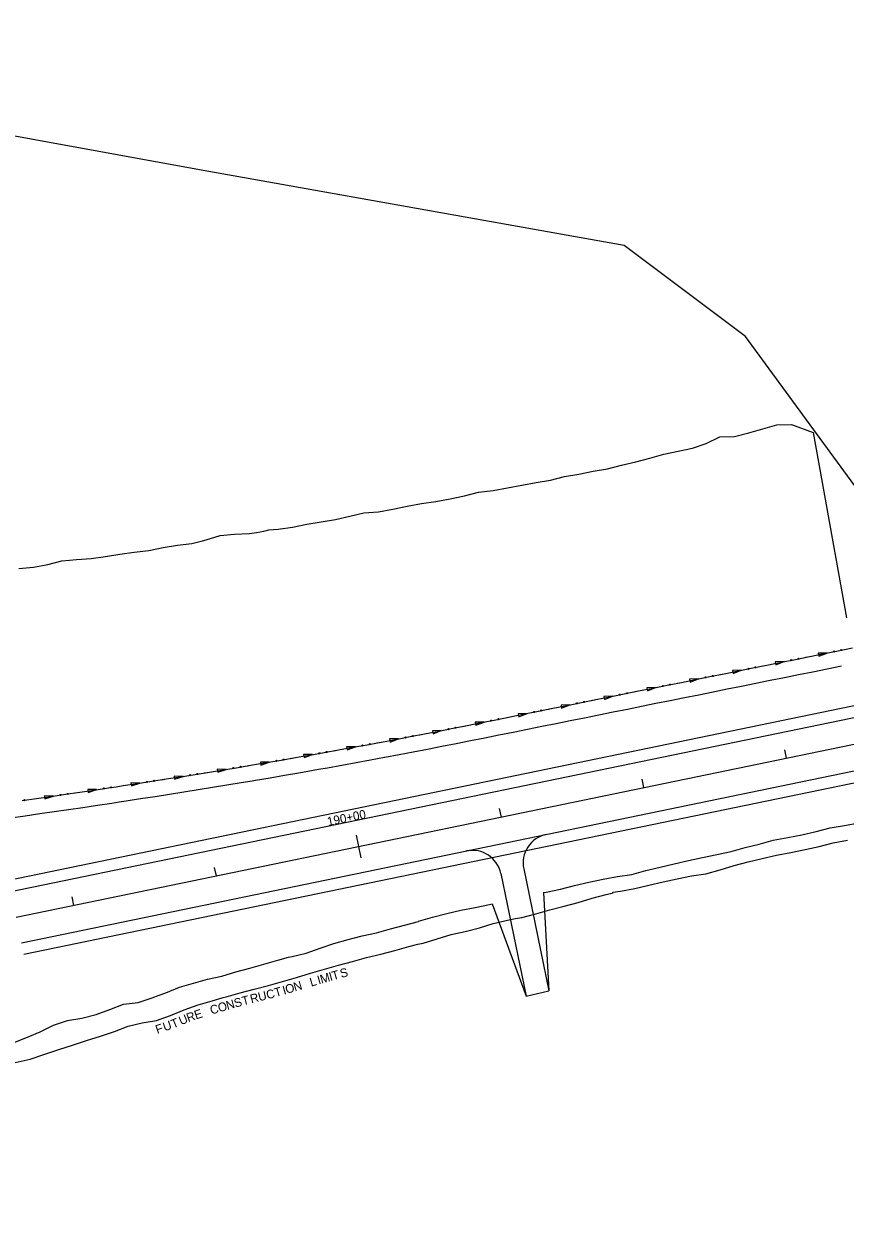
# Model space of a CAD drawing. Extents: x 979959 to 994833, y 1835619 to 1845316.
# Drawn here: x 984578 to 985142, y 1837559 to 1838378 of the extents above; entities that cross this region are included whole.
import ezdxf

# ---------------------------------------------------------------- set-up
doc = ezdxf.new("R2010")
doc.units = 0
for name, color, linetype in [('43', 7, 'Continuous'), ('Future 5 Lane Construction Limits', 7, 'Continuous'), ('R_Horz Alg', 7, 'Continuous'), ('R_Horz Alg Stationing', 7, 'Continuous'), ('R_Proposed Const Limits', 7, 'Continuous'), ('R_Proposed Road', 7, 'Continuous'), ('R_Special Ditch', 7, 'Continuous')]:
    doc.layers.add(name, color=color, linetype=linetype)

msp = doc.modelspace()

# ---------------------------------------------------------------- linework, layer by layer
at = {"layer": '43'}
msp.add_lwpolyline([(985729.8, 1837558.64), (985521.45, 1837673.22), (985396.47, 1837819.08), (985333.96, 1837902.41), (985188.08, 1838006.57), (985073.51, 1838162.87), (984990.18, 1838225.38), (984698.45, 1838277.45), (984469.3, 1838319.11), (984188, 1838277.43), (984135.93, 1838277.43), (984135.89, 1838350.34), (984198.39, 1838444.12), (984198.44, 1838496.23), (984083.82, 1838590), (983937.96, 1838704.54)], dxfattribs=at)
at = {"layer": 'Future 5 Lane Construction Limits'}
msp.add_lwpolyline([(984571.82, 1837664.17), (984582.07, 1837666.51), (984592.11, 1837669.83), (984601.66, 1837673.04), (984611.23, 1837676.15), (984620.8, 1837679.23), (984630.37, 1837682.34), (984639.92, 1837685.53), (984649.38, 1837689.17), (984659.11, 1837691.49), (984668.98, 1837693.17), (984678.5, 1837696.49), (984687.9, 1837700.43), (984697.43, 1837703.72), (984707.04, 1837706.62), (984714.65, 1837708.83), (984716.68, 1837709.4), (984726.33, 1837712.1), (984736.02, 1837714.62), (984745.73, 1837717.06), (984755.37, 1837719.83), (984764.99, 1837722.7), (984774.62, 1837725.52), (984784.25, 1837728.33), (984793.9, 1837731.04), (984803.57, 1837733.68), (984813.25, 1837736.25), (984822.97, 1837738.62), (984832.66, 1837741.13), (984842.29, 1837743.93), (984848.48, 1837745.42), (984852.02, 1837746.26), (984852.04, 1837746.26), (984861.62, 1837749.25), (984871.24, 1837752.11), (984881.01, 1837754.21), (984890.69, 1837756.83), (984900.29, 1837759.76), (984910.04, 1837761.98), (984915.54, 1837763.03), (984919.88, 1837763.81), (984929.58, 1837766.27), (984939.23, 1837768.99), (984948.88, 1837771.7), (984958.61, 1837774.04), (984968.17, 1837777.2), (984977.86, 1837779.69), (984982.59, 1837780.66), (984982.5, 1837781.14), (984987.59, 1837782.02), (984997.46, 1837783.68), (985007.21, 1837785.92), (985016.94, 1837788.26), (985026.71, 1837790.4), (985036.51, 1837792.4), (985046.4, 1837793.93), (985056.08, 1837796.5), (985065.67, 1837799.51), (985075.34, 1837802.15), (985085.09, 1837804.35), (985094.85, 1837806.57), (985104.66, 1837808.49), (985114.46, 1837810.5), (985124.22, 1837812.68), (985133.91, 1837815.18), (985143.75, 1837816.97)], dxfattribs=at)
at = {"layer": 'R_Horz Alg'}
msp.add_line((984572.47, 1837764.03), (990033.82, 1838891.48), dxfattribs=at)
at = {"layer": 'R_Horz Alg Stationing'}
for points in [[(985100.29, 1837879.12), (985101.5, 1837873.24)], [(985002.35, 1837858.9), (985003.57, 1837853.03)], [(984904.42, 1837838.68), (984905.63, 1837832.81)], [(984806.08, 1837820.43), (984809.32, 1837804.76)], [(984708.55, 1837798.25), (984709.76, 1837792.37)], [(984610.62, 1837778.03), (984611.83, 1837772.16)]]:
    msp.add_lwpolyline(points, dxfattribs=at)
at = {"layer": 'R_Proposed Const Limits'}
for p, q in [((984899.55, 1837773.2), (984922.87, 1837709.74)), ((984934.71, 1837780.92), (984938.42, 1837713.55))]:
    msp.add_line(p, q, dxfattribs=at)
for points in [[(984574.24, 1838003.67), (984584.29, 1838004.48), (984594.11, 1838006.36), (984603.83, 1838008.74), (984609.01, 1838009.36), (984613.84, 1838009.72), (984623.91, 1838010.42), (984633.81, 1838011.9), (984643.73, 1838013.32), (984653.64, 1838014.78), (984663.59, 1838016.01), (984673.38, 1838018.06), (984683.25, 1838019.72), (984693.24, 1838020.79), (984700.55, 1838022.53), (984702.94, 1838023.26), (984712.54, 1838026.2), (984722.56, 1838027.16), (984732.68, 1838027.58), (984737.63, 1838028.35), (984742.53, 1838029.33), (984746.13, 1838030.05), (984752.46, 1838030.7), (984762.42, 1838031.91), (984772.19, 1838034.04), (984782.08, 1838035.6), (984791.77, 1838037.26), (984791.78, 1838037.26), (984791.94, 1838037.29), (984801.71, 1838039.45), (984811.43, 1838041.8), (984821.5, 1838042.48), (984831.32, 1838044.4), (984841.11, 1838046.45), (984850.93, 1838048.32), (984860.89, 1838049.55), (984870.72, 1838051.4), (984880.47, 1838053.62), (984890.18, 1838056.03), (984900.17, 1838057.14), (984910.01, 1838058.92), (984919.82, 1838060.85), (984929.67, 1838062.58), (984939.53, 1838064.3), (984949.21, 1838066.85), (984959.09, 1838068.49), (984968.9, 1838070.39), (984978.78, 1838072.03), (984988.47, 1838074.56), (984998.2, 1838076.86), (985007.87, 1838079.49), (985017.55, 1838082.07), (985027.34, 1838084.1), (985037.09, 1838086.32), (985046.64, 1838089.52), (985055.91, 1838094.1), (985066.09, 1838094.25), (985075.76, 1838096.87), (985085.42, 1838099.51), (985095.06, 1838102.32), (985105.2, 1838102.62), (985120.09, 1838097.05), (985142.85, 1837969.72)], [(984934.71, 1837780.9), (984936.69, 1837781.31), (984946.5, 1837783.23), (984956.16, 1837785.91), (984965.9, 1837788.19), (984975.7, 1837790.2), (984985.54, 1837791.98), (984995.48, 1837793.29), (985005.09, 1837796.2), (985014.86, 1837798.34), (985024.56, 1837800.79), (985034.33, 1837802.91), (985044.13, 1837804.95), (985053.91, 1837807.02), (985063.68, 1837809.15), (985073.3, 1837812.01), (985083.06, 1837814.21), (985092.69, 1837817.01), (985102.55, 1837818.71), (985112.37, 1837820.61), (985122.09, 1837822.97), (985131.8, 1837825.39), (985141.69, 1837826.97), (985151.51, 1837828.83)], [(984569.27, 1837677.22), (984579.15, 1837681.07), (984588.9, 1837685.35), (984598.19, 1837689.82), (984607.74, 1837693.05), (984617.6, 1837694.72), (984627.31, 1837697.17), (984636.82, 1837700.56), (984646.28, 1837704.19), (984656.23, 1837705.48), (984665.8, 1837708.57), (984670.71, 1837710.52), (984675.29, 1837712.03), (984684.72, 1837715.85), (984694.32, 1837718.8), (984703.99, 1837721.42), (984713.77, 1837723.5), (984723.35, 1837726.55), (984733.06, 1837729), (984742.69, 1837731.78), (984752.32, 1837734.62), (984759.57, 1837736.66), (984762.05, 1837736.94), (984771.77, 1837739.34), (984781.27, 1837742.77), (984790.81, 1837746.01), (984800.47, 1837748.7), (984804.03, 1837749.61), (984810.17, 1837751.16), (984819.92, 1837753.38), (984829.59, 1837755.99), (984839.28, 1837758.52), (984848.8, 1837761), (984848.74, 1837761.34), (984848.9, 1837761.39), (984858.57, 1837764.03), (984868.25, 1837766.6), (984877.99, 1837768.86), (984887.83, 1837770.67), (984897.63, 1837772.67), (984899.55, 1837773.2)]]:
    msp.add_lwpolyline(points, dxfattribs=at)
at = {"layer": 'R_Proposed Road'}
for p, q in [((984567.22, 1837789.49), (990028.56, 1838916.94)), ((984568.84, 1837781.66), (990030.18, 1838909.11)), ((984576.11, 1837746.4), (990037.46, 1838873.85)), ((984577.73, 1837738.57), (990039.08, 1838866.02)), ((984922.87, 1837709.74), (984938.42, 1837713.55))]:
    msp.add_line(p, q, dxfattribs=at)
for points in [[(984905.48, 1837793.98), (984922.87, 1837709.74)], [(984921.15, 1837797.21), (984938.42, 1837713.55)]]:
    msp.add_lwpolyline(points, dxfattribs=at)
for centre, start, end in [((984940.74, 1837801.25), 101.66438, 191.66438), ((984885.89, 1837789.93), 11.66438, 101.66438)]:
    msp.add_arc(centre, 20, start, end, dxfattribs=at)
at = {"layer": 'R_Special Ditch'}
for p, q in [((985129.59, 1837945.52), (985123.5, 1837945.37)), ((985123.5, 1837945.37), (985123.92, 1837943.3)), ((985123.92, 1837943.3), (985129.59, 1837945.52)), ((985100.15, 1837939.59), (985094.06, 1837939.44)), ((985094.06, 1837939.44), (985094.47, 1837937.37)), ((985094.47, 1837937.37), (985100.15, 1837939.59)), ((985070.7, 1837933.66), (985064.61, 1837933.51)), ((985064.61, 1837933.51), (985065.03, 1837931.44)), ((985065.03, 1837931.44), (985070.7, 1837933.66)), ((985011.81, 1837921.79), (985005.72, 1837921.65)), ((985005.72, 1837921.65), (985006.14, 1837919.57)), ((985006.14, 1837919.57), (985011.81, 1837921.79)), ((985041.25, 1837927.73), (985035.16, 1837927.58)), ((985035.16, 1837927.58), (985035.58, 1837925.5)), ((985035.58, 1837925.5), (985041.25, 1837927.73)), ((984982.36, 1837915.86), (984976.27, 1837915.71)), ((984976.27, 1837915.71), (984976.69, 1837913.64)), ((984976.69, 1837913.64), (984982.36, 1837915.86)), ((984952.91, 1837909.93), (984946.82, 1837909.78)), ((984946.82, 1837909.78), (984947.24, 1837907.71)), ((984947.24, 1837907.71), (984952.91, 1837909.93)), ((984894.02, 1837898.06), (984887.93, 1837897.92)), ((984887.93, 1837897.92), (984888.35, 1837895.85)), ((984888.35, 1837895.85), (984894.02, 1837898.06)), ((984923.47, 1837904), (984917.38, 1837903.85)), ((984917.38, 1837903.85), (984917.8, 1837901.78)), ((984917.8, 1837901.78), (984923.47, 1837904)), ((984864.56, 1837892.21), (984858.47, 1837892.11)), ((984858.47, 1837892.11), (984858.87, 1837890.03)), ((984858.87, 1837890.03), (984864.56, 1837892.21)), ((984805.53, 1837881.04), (984799.44, 1837881.01)), ((984799.44, 1837881.01), (984799.82, 1837878.93)), ((984799.82, 1837878.93), (984805.53, 1837881.04)), ((984835.06, 1837886.54), (984828.97, 1837886.47)), ((984828.97, 1837886.47), (984829.36, 1837884.39)), ((984829.36, 1837884.39), (984835.06, 1837886.54)), ((984775.97, 1837875.73), (984769.88, 1837875.73)), ((984769.88, 1837875.73), (984770.24, 1837873.65)), ((984770.24, 1837873.65), (984775.97, 1837875.73)), ((984716.75, 1837865.61), (984710.66, 1837865.68)), ((984710.66, 1837865.68), (984711, 1837863.59)), ((984711, 1837863.59), (984716.75, 1837865.61)), ((984746.37, 1837870.59), (984740.28, 1837870.63)), ((984740.28, 1837870.63), (984740.63, 1837868.55)), ((984740.63, 1837868.55), (984746.37, 1837870.59)), ((984657.42, 1837856.16), (984651.33, 1837856.3)), ((984651.33, 1837856.3), (984651.65, 1837854.21)), ((984651.65, 1837854.21), (984657.42, 1837856.16)), ((984687.1, 1837860.79), (984681.01, 1837860.9)), ((984681.01, 1837860.9), (984681.34, 1837858.81)), ((984681.34, 1837858.81), (984687.1, 1837860.79)), ((984598.01, 1837847.25), (984591.92, 1837847.45)), ((984591.92, 1837847.45), (984592.22, 1837845.35)), ((984592.22, 1837845.35), (984598.01, 1837847.25)), ((984627.73, 1837851.65), (984621.64, 1837851.81)), ((984621.64, 1837851.81), (984621.95, 1837849.71)), ((984621.95, 1837849.71), (984627.73, 1837851.65))]:
    msp.add_line(p, q, dxfattribs=at)
for points in [[(984576.53, 1837844.19), (984586.46, 1837845.6), (984596.37, 1837847.02), (984606.29, 1837848.46), (984616.2, 1837849.92), (984626.1, 1837851.4), (984636, 1837852.91), (984641.15, 1837853.69), (984645.9, 1837854.41), (984655.8, 1837855.91), (984665.7, 1837857.43), (984675.59, 1837858.98), (984685.48, 1837860.54), (984695.36, 1837862.12), (984705.24, 1837863.72), (984715.12, 1837865.34), (984724.99, 1837866.98), (984732.4, 1837868.23), (984734.86, 1837868.64), (984744.73, 1837870.31), (984754.59, 1837872), (984764.45, 1837873.71), (984769.38, 1837874.57), (984774.3, 1837875.43), (984777.92, 1837876.07), (984784.15, 1837877.18), (984794, 1837878.95), (984803.84, 1837880.73), (984813.68, 1837882.54), (984823.34, 1837884.33), (984823.35, 1837884.34), (984823.51, 1837884.37), (984833.34, 1837886.21), (984843.17, 1837888.08), (984852.99, 1837889.97), (984862.81, 1837891.87), (984872.62, 1837893.8), (984882.43, 1837895.74), (984892.24, 1837897.71), (984902.04, 1837899.68), (984911.84, 1837901.66), (984921.64, 1837903.63), (984931.45, 1837905.61), (984941.25, 1837907.58), (984951.05, 1837909.56), (984960.86, 1837911.53), (984970.66, 1837913.5), (984980.46, 1837915.48), (984990.27, 1837917.45), (985000.07, 1837919.43), (985009.87, 1837921.4), (985019.68, 1837923.38), (985029.48, 1837925.35), (985039.28, 1837927.33), (985049.09, 1837929.3), (985058.89, 1837931.28), (985068.69, 1837933.25), (985078.5, 1837935.23), (985088.3, 1837937.2), (985098.1, 1837939.18), (985107.91, 1837941.15), (985117.71, 1837943.13), (985127.51, 1837945.1), (985137.31, 1837947.08), (985147.12, 1837949.05)], [(985114.89, 1837942.56), (985117.71, 1837943.13), (985127.51, 1837945.1), (985129.59, 1837945.52)], [(985085.44, 1837936.63), (985088.3, 1837937.2), (985098.1, 1837939.18), (985100.15, 1837939.59)], [(985114.85, 1837942.55), (985114.89, 1837942.56)], [(984568.76, 1837832.38), (984578.69, 1837833.76), (984588.61, 1837835.17), (984598.53, 1837836.59), (984608.44, 1837838.03), (984618.35, 1837839.49), (984628.25, 1837840.97), (984638.15, 1837842.47), (984643.3, 1837843.26), (984648.06, 1837843.98), (984657.96, 1837845.48), (984667.85, 1837847), (984677.74, 1837848.55), (984687.63, 1837850.11), (984697.52, 1837851.69), (984707.4, 1837853.29), (984717.27, 1837854.91), (984727.15, 1837856.55), (984734.56, 1837857.8), (984737.01, 1837858.21), (984746.88, 1837859.88), (984756.74, 1837861.57), (984766.6, 1837863.28), (984776.46, 1837865), (984780.07, 1837865.64), (984786.31, 1837866.75), (984796.15, 1837868.52), (984805.99, 1837870.3), (984815.83, 1837872.11), (984825.49, 1837873.9), (984825.5, 1837873.91), (984825.67, 1837873.94), (984835.5, 1837875.78), (984845.32, 1837877.65), (984855.14, 1837879.54), (984864.96, 1837881.44), (984874.77, 1837883.37), (984884.58, 1837885.31), (984894.39, 1837887.28), (984904.19, 1837889.25), (984913.99, 1837891.23), (984923.8, 1837893.2), (984933.6, 1837895.18), (984943.4, 1837897.15), (984953.21, 1837899.13), (984963.01, 1837901.1), (984972.81, 1837903.07), (984982.62, 1837905.05), (984992.42, 1837907.02), (985002.22, 1837909), (985012.03, 1837910.97), (985021.83, 1837912.95), (985031.63, 1837914.92), (985041.44, 1837916.9), (985051.24, 1837918.87), (985061.04, 1837920.85), (985070.85, 1837922.82), (985080.65, 1837924.8), (985090.45, 1837926.77), (985100.26, 1837928.75), (985110.06, 1837930.72), (985119.86, 1837932.7), (985129.66, 1837934.67), (985139.47, 1837936.65)], [(985055.96, 1837930.69), (985056, 1837930.69)], [(985056, 1837930.69), (985058.89, 1837931.28), (985068.69, 1837933.25), (985070.7, 1837933.66)], [(985085.41, 1837936.62), (985085.44, 1837936.63)], [(984997.1, 1837918.83), (985000.07, 1837919.43), (985009.87, 1837921.4), (985011.81, 1837921.79)], [(985026.51, 1837924.76), (985026.55, 1837924.76)], [(985026.55, 1837924.76), (985029.48, 1837925.35), (985039.28, 1837927.33), (985041.25, 1837927.73)], [(984967.62, 1837912.89), (984967.66, 1837912.9)], [(984967.66, 1837912.9), (984970.66, 1837913.5), (984980.46, 1837915.48), (984982.36, 1837915.86)], [(984997.07, 1837918.82), (984997.1, 1837918.83)], [(984938.17, 1837906.96), (984938.21, 1837906.97)], [(984938.21, 1837906.97), (984941.25, 1837907.58), (984951.05, 1837909.56), (984952.91, 1837909.93)], [(984879.31, 1837895.12), (984882.43, 1837895.74), (984892.24, 1837897.71), (984894.02, 1837898.07)], [(984908.73, 1837901.03), (984908.76, 1837901.04)], [(984908.76, 1837901.04), (984911.84, 1837901.66), (984921.64, 1837903.63), (984923.47, 1837904)], [(984849.8, 1837889.35), (984849.83, 1837889.36)], [(984849.83, 1837889.36), (984852.99, 1837889.97), (984862.81, 1837891.87), (984864.56, 1837892.22)], [(984879.28, 1837895.12), (984879.31, 1837895.12)], [(984790.77, 1837878.37), (984794, 1837878.95), (984803.84, 1837880.73), (984805.53, 1837881.05)], [(984820.28, 1837883.77), (984820.32, 1837883.77)], [(984820.32, 1837883.77), (984823.34, 1837884.33), (984823.35, 1837884.34), (984823.51, 1837884.37), (984833.34, 1837886.21), (984835.06, 1837886.54)], [(984761.15, 1837873.14), (984761.19, 1837873.14)], [(984761.19, 1837873.14), (984764.45, 1837873.71), (984769.38, 1837874.57), (984774.3, 1837875.43), (984775.97, 1837875.73)], [(984790.73, 1837878.36), (984790.77, 1837878.37)], [(984701.91, 1837863.18), (984701.95, 1837863.19)], [(984701.95, 1837863.19), (984705.24, 1837863.72), (984715.12, 1837865.34), (984716.75, 1837865.61)], [(984731.54, 1837868.09), (984731.58, 1837868.09)], [(984731.58, 1837868.09), (984732.4, 1837868.23), (984734.86, 1837868.64), (984744.73, 1837870.31), (984746.37, 1837870.59)], [(984642.59, 1837853.91), (984645.9, 1837854.41), (984655.8, 1837855.91), (984657.42, 1837856.16)], [(984672.25, 1837858.45), (984672.28, 1837858.46)], [(984672.28, 1837858.46), (984675.59, 1837858.98), (984685.48, 1837860.54), (984687.1, 1837860.8)], [(984583.16, 1837845.13), (984586.46, 1837845.6), (984596.37, 1837847.02), (984598.01, 1837847.26)], [(984612.85, 1837849.43), (984612.89, 1837849.43)], [(984612.89, 1837849.43), (984616.2, 1837849.92), (984626.1, 1837851.4), (984627.73, 1837851.65)], [(984642.55, 1837853.9), (984642.59, 1837853.91)], [(984583.12, 1837845.12), (984583.16, 1837845.13)]]:
    msp.add_lwpolyline(points, dxfattribs=at)
for centre in [(985134.49, 1837946.54), (985139.41, 1837947.53), (985105.05, 1837940.61), (985109.96, 1837941.6), (985046.15, 1837928.75), (985051.07, 1837929.74), (985075.6, 1837934.68), (985080.51, 1837935.67), (985016.71, 1837922.82), (985021.62, 1837923.81), (984962.73, 1837911.94), (984987.26, 1837916.89), (984992.17, 1837917.88), (984928.37, 1837905.02), (984933.28, 1837906.01), (984957.82, 1837910.95), (984898.92, 1837899.09), (984903.83, 1837900.08), (984839.97, 1837887.51), (984844.89, 1837888.45), (984869.46, 1837893.21), (984874.38, 1837894.18), (984810.45, 1837881.99), (984815.38, 1837882.89), (984751.3, 1837871.47), (984756.24, 1837872.32), (984780.89, 1837876.64), (984785.82, 1837877.52), (984721.68, 1837866.47), (984726.62, 1837867.3), (984662.36, 1837856.96), (984667.32, 1837857.72), (984692.04, 1837861.62), (984696.98, 1837862.42), (984602.96, 1837848.01), (984607.92, 1837848.74), (984632.67, 1837852.44), (984637.62, 1837853.19), (984578.18, 1837844.46)]:
    msp.add_circle(centre, 0.375, dxfattribs=at)

# ---------------------------------------------------------------- texts
at = {"layer": 'Future 5 Lane Construction Limits'}
for s, rotation, p in [('I', 16.29025, (984780.3, 1837717.8)), ('M', 16.29025, (984782.21, 1837718.36)), ('I', 15.65747, (984788.32, 1837720.13)), ('T', 15.65747, (984790.23, 1837720.66)), ('S', 15.3071, (984795.83, 1837722.24)), ('T', 16.0174, (984750.76, 1837709.14)), ('I', 16.62647, (984756.46, 1837710.76)), ('O', 16.62647, (984758.36, 1837711.33)), ('N', 16.62647, (984763.98, 1837713)), ('L', 16.29025, (984775.13, 1837716.29)), ('N', 15.6462, (984717.58, 1837700.31)), ('S', 15.6462, (984723.04, 1837701.84)), ('T', 14.57849, (984728.39, 1837703.34)), ('R', 14.57849, (984734.06, 1837704.81)), ('U', 14.09519, (984739.5, 1837706.22)), ('C', 14.09519, (984745.09, 1837707.62)), ('E', 19.04194, (984696.02, 1837693.71)), ('C', 16.78129, (984706.64, 1837697.09)), ('O', 16.20122, (984712.01, 1837698.69)), ('U', 19.2061, (984674.48, 1837685.56)), ('T', 22.73867, (984680.31, 1837687.49)), ('U', 22.73867, (984685.71, 1837689.75)), ('R', 19.04194, (984690.66, 1837691.86)), ('F', 19.2061, (984669.39, 1837683.79))]:
    msp.add_text(s, height=6, rotation=rotation, dxfattribs=at).set_placement(p)
at = {"layer": 'R_Horz Alg Stationing'}
msp.add_text('190+00', height=6, rotation=11.66438, dxfattribs=at).set_placement((984786.78, 1837826.65))

doc.saveas('drawing.dxf')
